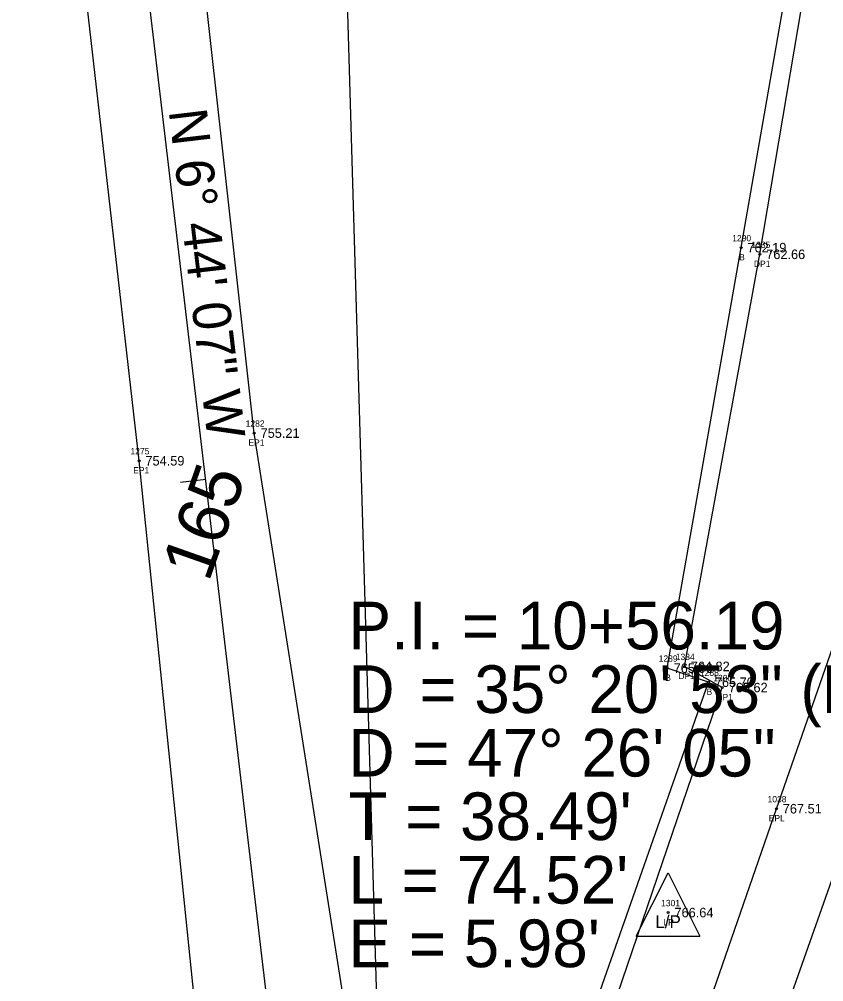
# Model space of a CAD drawing. Extents: x 1736563 to 1738032, y 1150548 to 1154248.
# Drawn here: x 1736807.2 to 1736933.8, y 1151294.7 to 1151446.2 of the extents above; entities that cross this region are included whole.
import ezdxf

# ---------------------------------------------------------------- set-up
doc = ezdxf.new("R2010")
doc.units = 0
for name, color, linetype in [('RD_EX_Bldg', 7, 'Continuous'), ('RD_EX_Bldg_txCode', 7, 'Continuous'), ('RD_EX_Driveway', 7, 'Continuous'), ('RD_EX_Driveway_txCode', 7, 'Continuous'), ('RD_EX_Road', 7, 'Continuous'), ('RD_EX_Road_txCode', 7, 'Continuous'), ('RD_EX_TX_Bldg_ELEV', 7, 'Continuous'), ('RD_EX_TX_Driveway_ELEV', 7, 'Continuous'), ('RD_EX_TX_Road_ELEV', 7, 'Continuous'), ('RD_EX_TX_UT_ELEV', 7, 'Continuous'), ('RD_EX_UT', 7, 'Continuous'), ('RD_EX_UT_txCode', 7, 'Continuous'), ('RD_HC_Cl', 7, 'Continuous'), ('RD_HC_Data', 7, 'Continuous'), ('RD_HC_Data_Tic', 7, 'Continuous'), ('RD_HC_TX_Sta50', 7, 'Continuous'), ('RD_SMD_Locator', 7, 'Continuous')]:
    doc.layers.add(name, color=color, linetype=linetype)

msp = doc.modelspace()

# ---------------------------------------------------------------- linework, layer by layer
at = {"layer": 'RD_EX_Bldg'}
msp.add_lwpolyline([(1736863.77, 1151279.47), (1736867.06, 1151267.94), (1736888.13, 1151263.51), (1736915.64, 1151341.84), (1736909.15, 1151344.06), (1736920.76, 1151410.23), (1736929.45, 1151459.89), (1736858.09, 1151472.21), (1736863.77, 1151279.47)], dxfattribs=at)
at = {"layer": 'RD_EX_Driveway'}
msp.add_lwpolyline([(1736911.77, 1151279.81), (1736898.18, 1151283.49), (1736917.81, 1151341), (1736911.84, 1151344.33), (1736923.72, 1151409.18), (1736933.3, 1151466.02), (1736937.76, 1151483.42), (1736947.15, 1151475.11), (1736970.42, 1151464.99), (1736977.6, 1151467.57)], dxfattribs=at)
at = {"layer": 'RD_EX_Road'}
for points in [[(1736868.01, 1151157.6), (1736882.54, 1151196.52), (1736892.4, 1151226.58), (1736911.77, 1151279.81), (1736926.32, 1151321.94), (1736959.92, 1151418.27), (1736977.6, 1151467.57), (1736993.86, 1151514.24), (1737026.63, 1151607.21), (1737059.17, 1151698.64), (1737091.53, 1151790.84), (1737119.9, 1151870.3), (1737125.51, 1151887.21), (1737129.74, 1151897.31), (1737157.61, 1151979.19), (1737191.07, 1152073.18), (1737224.57, 1152167.62), (1737258.08, 1152262.33), (1737292.51, 1152359.5), (1737326.83, 1152457.35), (1737361.84, 1152556.63), (1737380.81, 1152611.37), (1737392.07, 1152607.38)], [(1736892.4, 1151226.58), (1736882.22, 1151227.11), (1736872.42, 1151233.52), (1736863.72, 1151257.25), (1736844.16, 1151381.05), (1736831.55, 1151494.33), (1736825.62, 1151545.71)], [(1736868.01, 1151157.6), (1736869.22, 1151173.32), (1736864.67, 1151193.4), (1736847.18, 1151224.87), (1736838.98, 1151250.85), (1736826.04, 1151376.69), (1736812.87, 1151492.03), (1736807.18, 1151542.68)]]:
    msp.add_lwpolyline(points, dxfattribs=at)
at = {"layer": 'RD_EX_UT'}
for p, q in [((1736904.28, 1151301.87), (1736909.28, 1151311.87)), ((1736909.28, 1151311.87), (1736914.28, 1151301.87)), ((1736904.28, 1151301.87), (1736914.28, 1151301.87))]:
    msp.add_line(p, q, dxfattribs=at)
at = {"layer": 'RD_HC_Cl'}
for p, q in [((1736879.96, 1151154.46), (1737935.1, 1154148.31)), ((1736849.17, 1151266.7), (1736816.4, 1151544.19))]:
    msp.add_line(p, q, dxfattribs=at)
at = {"layer": 'RD_HC_Data_Tic'}
msp.add_line((1736836.53, 1151373.73), (1736832.56, 1151373.26), dxfattribs=at)
at = {"layer": 'RD_SMD_Locator'}
for centre in [(1736920.76, 1151410.23), (1736923.72, 1151409.18), (1736844.16, 1151381.05), (1736826.04, 1151376.69), (1736911.84, 1151344.33), (1736909.15, 1151344.06), (1736915.64, 1151341.84), (1736917.81, 1151341), (1736926.32, 1151321.94), (1736909.28, 1151305.59)]:
    msp.add_circle(centre, 0.15, dxfattribs=at)

# ---------------------------------------------------------------- texts
at = {"layer": 'RD_EX_Bldg_txCode'}
for s, p in [('1290', (1736919.37, 1151411.23)), ('B', (1736920.45, 1151408.23)), ('1289', (1736907.8, 1151345.06)), ('B', (1736908.84, 1151342.06)), ('1288', (1736914.29, 1151342.84)), ('B', (1736915.33, 1151339.84))]:
    msp.add_text(s, height=1, dxfattribs=at).set_placement(p)
at = {"layer": 'RD_EX_Driveway_txCode'}
for s, p in [('1335', (1736922.38, 1151410.18)), ('DP1', (1736922.78, 1151407.18)), ('1334', (1736910.49, 1151345.33)), ('DP1', (1736910.89, 1151342.33)), ('1300', (1736916.39, 1151342)), ('DP1', (1736916.87, 1151339))]:
    msp.add_text(s, height=1, dxfattribs=at).set_placement(p)
at = {"layer": 'RD_EX_Road_txCode'}
for s, p in [('1282', (1736842.81, 1151382.05)), ('EP1', (1736843.24, 1151379.05)), ('1275', (1736824.69, 1151377.69)), ('EP1', (1736825.11, 1151374.69)), ('1038', (1736924.93, 1151322.94)), ('EPL', (1736925.11, 1151319.94))]:
    msp.add_text(s, height=1, dxfattribs=at).set_placement(p)
at = {"layer": 'RD_EX_TX_Bldg_ELEV'}
for s, p in [('762.19', (1736921.76, 1151409.48)), ('765.06', (1736910.15, 1151343.31)), ('765.70', (1736916.64, 1151341.09))]:
    msp.add_text(s, height=1.5, dxfattribs=at).set_placement(p)
at = {"layer": 'RD_EX_TX_Driveway_ELEV'}
for s, p in [('762.66', (1736924.72, 1151408.43)), ('764.82', (1736912.84, 1151343.58)), ('765.62', (1736918.81, 1151340.25))]:
    msp.add_text(s, height=1.5, dxfattribs=at).set_placement(p)
at = {"layer": 'RD_EX_TX_Road_ELEV'}
for s, p in [('755.21', (1736845.16, 1151380.3)), ('754.59', (1736827.04, 1151375.94)), ('767.51', (1736927.32, 1151321.19))]:
    msp.add_text(s, height=1.5, dxfattribs=at).set_placement(p)
at = {"layer": 'RD_EX_TX_UT_ELEV'}
msp.add_text('766.64', height=1.5, dxfattribs=at).set_placement((1736910.28, 1151304.84))
at = {"layer": 'RD_EX_UT'}
msp.add_text('L/P', height=2, dxfattribs=at).set_placement((1736907.27, 1151303.15))
at = {"layer": 'RD_EX_UT_txCode'}
for s, p in [('1301', (1736908.18, 1151306.59)), ('LP', (1736908.53, 1151303.59))]:
    msp.add_text(s, height=1, dxfattribs=at).set_placement(p)
at = {"layer": 'RD_HC_Data'}
msp.add_text('N 6%%d 44\' 07" W', height=6, rotation=276.7353, dxfattribs=at).set_placement((1736830.69, 1151431.77))
for s, p in [('P.I. = 10+56.19', (1736859, 1151347)), ('D', (1736859, 1151337)), ('    = 35%%d 20\' 53" (RT)', (1736859, 1151337)), ('D = 47%%d 26\' 05"', (1736859, 1151327)), ("T = 38.49'", (1736859, 1151317)), ("L = 74.52'", (1736859, 1151307)), ("E = 5.98'", (1736859, 1151297))]:
    msp.add_text(s, height=7.5, dxfattribs=at).set_placement(p)
at = {"layer": 'RD_HC_TX_Sta50'}
msp.add_text('165', height=8, rotation=70.5857, dxfattribs=at).set_placement((1736836.98, 1151357.43))

doc.saveas('drawing.dxf')
